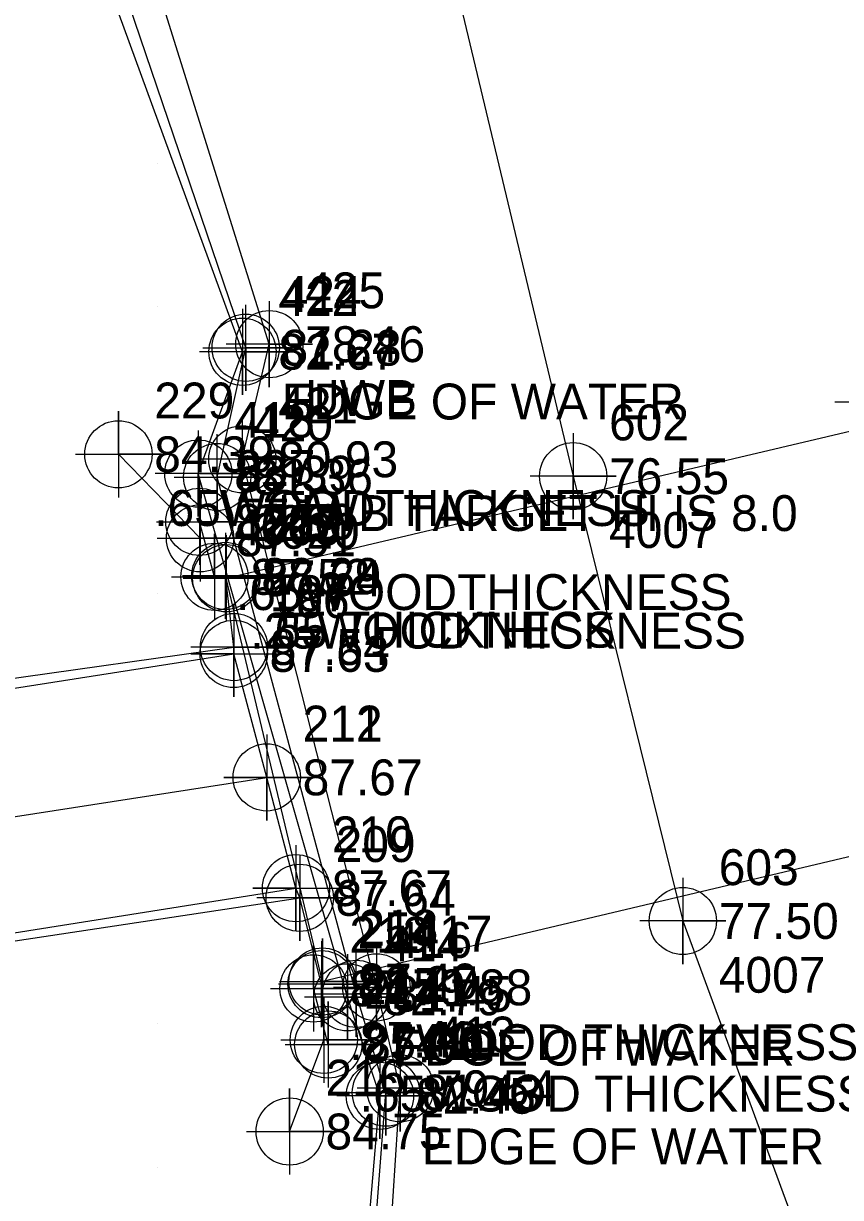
# Model space of a CAD drawing. Extents: x 1988140 to 1988766, y 249950 to 250250.
# Drawn here: x 1988400.7 to 1988457.6, y 250027.9 to 250109.7 of the extents above; entities that cross this region are included whole.
import ezdxf

# ---------------------------------------------------------------- set-up
doc = ezdxf.new("R2010")
doc.units = 0
for name, color, linetype in [('Exist DTM Breakline', 7, 'Continuous'), ('Exist DTM Breakline Cogo Comment', 7, 'Continuous'), ('Exist DTM Breakline Cogo Elevation', 7, 'Continuous'), ('Exist DTM Breakline Cogo Number', 7, 'Continuous'), ('Exist DTM Breakline Cogo Point CELL', 7, 'Continuous'), ('Exist DTM Breakline Underwater', 7, 'Continuous'), ('Exist DTM Breakline Underwater Cogo Comment', 7, 'Continuous'), ('Exist DTM Breakline Underwater Cogo Elevation', 7, 'Continuous'), ('Exist DTM Breakline Underwater Cogo Number', 7, 'Continuous'), ('Exist DTM Breakline Underwater Cogo Point CELL', 7, 'Continuous'), ('Exist DTM Crownline', 7, 'Continuous'), ('Exist DTM Crownline Cogo Elevation', 7, 'Continuous'), ('Exist DTM Crownline Cogo Number', 7, 'Continuous'), ('Exist DTM Crownline Cogo Point CELL', 7, 'Continuous'), ('Exist DTM QL2 LIDAR Elevation Point', 7, 'Continuous'), ('Exist Hydro Stream or Body of Water', 7, 'Continuous'), ('Exist Hydro Stream or Body of Water Cogo Comment', 7, 'Continuous'), ('Exist Hydro Stream or Body of Water Cogo Elevation', 7, 'Continuous'), ('Exist Hydro Stream or Body of Water Cogo Number', 7, 'Continuous'), ('Exist Hydro Stream or Body of Water Cogo Point CELL', 7, 'Continuous'), ('Exist Roads Change in Surface', 7, 'Continuous'), ('Exist Roads EOP', 7, 'Continuous'), ('Exist Roads EOP Cogo Comment', 7, 'Continuous'), ('Exist Roads EOP Cogo Elevation', 7, 'Continuous'), ('Exist Roads EOP Cogo Number', 7, 'Continuous'), ('Exist Roads EOP Cogo Point CELL', 7, 'Continuous'), ('Exist Roads EOT', 7, 'Continuous'), ('Exist Roads EOT Cogo Elevation', 7, 'Continuous'), ('Exist Roads EOT Cogo Number', 7, 'Continuous'), ('Exist Roads EOT Cogo Point CELL', 7, 'Continuous'), ('Exist Structure Major Bridge WW', 7, 'Continuous'), ('Exist Structure Major Deck Tunnel Box Culvert', 7, 'Continuous'), ('Exist Structure Major Deck Tunnel Box Culvert Cogo Elevation', 7, 'Continuous'), ('Exist Structure Major Deck Tunnel Box Culvert Cogo Number', 7, 'Continuous'), ('Exist Structure Major Deck Tunnel Box Culvert Cogo Point CELL', 7, 'Continuous'), ('Exist Structure Minor Head and End Wall Cogo Comment', 7, 'Continuous'), ('Exist Structure Minor Head and End Wall Cogo Elevation', 7, 'Continuous'), ('Exist Structure Minor Head and End Wall Cogo Number', 7, 'Continuous'), ('Exist Structure Minor Head and End Wall Cogo Point CELL', 7, 'Continuous')]:
    doc.layers.add(name, color=color, linetype=linetype)

msp = doc.modelspace()

# ---------------------------------------------------------------- linework, layer by layer
at = {"layer": 'Exist DTM Breakline'}
for points in [[(1988412.8446, 250078.35), (1988415.9225, 250086.8449), (1988404.9645, 250116.8632), (1988400.2626, 250127.7783), (1988397.8753, 250146.5011), (1988407.465, 250191.587)], [(1988432.5356, 249952.6918), (1988424.6294, 249989.0571), (1988424.2247, 250020.0082), (1988425.5053, 250034.9767), (1988423.2372, 250041.8418), (1988412.8446, 250078.35)]]:
    msp.add_lwpolyline(points, dxfattribs=at)
at = {"layer": 'Exist DTM Breakline Cogo Point CELL'}
for points in [[(1988417.7936, 250090.3716), (1988417.7936, 250084.3716), (1988417.7936, 250087.3716), (1988420.7936, 250087.3716), (1988414.7936, 250087.3716)], [(1988415.9225, 250089.8449), (1988415.9225, 250083.8449), (1988415.9225, 250086.8449), (1988418.9225, 250086.8449), (1988412.9225, 250086.8449)], [(1988460.2177, 250086.319), (1988460.2177, 250080.319), (1988460.2177, 250083.319), (1988463.2177, 250083.319), (1988457.2177, 250083.319)], [(1988415.9105, 250082.3465), (1988415.9105, 250076.3465), (1988415.9105, 250079.3465), (1988418.9105, 250079.3465), (1988412.9105, 250079.3465)], [(1988412.8446, 250081.35), (1988412.8446, 250075.35), (1988412.8446, 250078.35), (1988415.8446, 250078.35), (1988409.8446, 250078.35)], [(1988425.2614, 250045.5346), (1988425.2614, 250039.5346), (1988425.2614, 250042.5346), (1988428.2614, 250042.5346), (1988422.2614, 250042.5346)], [(1988423.2372, 250044.8418), (1988423.2372, 250038.8418), (1988423.2372, 250041.8418), (1988426.2372, 250041.8418), (1988420.2372, 250041.8418)], [(1988426.9175, 250038.4976), (1988426.9175, 250032.4976), (1988426.9175, 250035.4976), (1988429.9175, 250035.4976), (1988423.9175, 250035.4976)], [(1988425.5053, 250037.9767), (1988425.5053, 250031.9767), (1988425.5053, 250034.9767), (1988428.5053, 250034.9767), (1988422.5053, 250034.9767)]]:
    msp.add_lwpolyline(points, dxfattribs=at)
for centre in [(1988415.9225, 250086.8449), (1988417.7936, 250087.3716), (1988415.9105, 250079.3465), (1988412.8446, 250078.35), (1988423.2372, 250041.8418), (1988425.2614, 250042.5346), (1988426.9175, 250035.4976), (1988425.5053, 250034.9767)]:
    msp.add_circle(centre, 2.344, dxfattribs=at)
at = {"layer": 'Exist DTM Breakline Underwater'}
for points in [[(1988432.5434, 250186.7094), (1988425.7037, 250133.7144), (1988438.98, 250078.1677), (1988446.627, 250047.162), (1988463.2661, 250001.9742), (1988462.1612, 249955.3502)], [(1988417.7936, 250087.3716), (1988408.4707, 250117.1773), (1988402.0332, 250128.5975)], [(1988436.1327, 249955.9094), (1988427.138, 249990.9941), (1988425.95, 250020.4466), (1988426.9175, 250035.4976), (1988425.2614, 250042.5346), (1988415.9105, 250079.3465), (1988417.7936, 250087.3716)]]:
    msp.add_lwpolyline(points, dxfattribs=at)
at = {"layer": 'Exist DTM Breakline Underwater Cogo Point CELL'}
for points in [[(1988438.98, 250081.1677), (1988438.98, 250075.1677), (1988438.98, 250078.1677), (1988441.98, 250078.1677), (1988435.98, 250078.1677)], [(1988446.627, 250050.162), (1988446.627, 250044.162), (1988446.627, 250047.162), (1988449.627, 250047.162), (1988443.627, 250047.162)]]:
    msp.add_lwpolyline(points, dxfattribs=at)
for centre in [(1988438.98, 250078.1677), (1988446.627, 250047.162)]:
    msp.add_circle(centre, 2.344, dxfattribs=at)
at = {"layer": 'Exist DTM Crownline'}
msp.add_lwpolyline([(1988342.6848, 250048.4444), (1988378.1968, 250051.0543), (1988417.6158, 250057.1729)], dxfattribs=at)
at = {"layer": 'Exist DTM Crownline Cogo Point CELL'}
msp.add_lwpolyline([(1988417.6158, 250060.1729), (1988417.6158, 250054.1729), (1988417.6158, 250057.1729), (1988420.6158, 250057.1729), (1988414.6158, 250057.1729)], dxfattribs=at)
msp.add_circle((1988417.6158, 250057.1729), 2.344, dxfattribs=at)
at = {"layer": 'Exist DTM QL2 LIDAR Elevation Point'}
for p, q in [((1988410, 250100), (1988410, 250100)), ((1988410, 250090), (1988410, 250090)), ((1988410, 250070), (1988410, 250070)), ((1988410, 250040), (1988410, 250040)), ((1988410, 250030), (1988410, 250030)), ((1988420, 250030), (1988420, 250030))]:
    msp.add_line(p, q, dxfattribs=at)
at = {"layer": 'Exist Hydro Stream or Body of Water'}
msp.add_lwpolyline([(1988426.3876, 249990.4525), (1988424.7619, 250020.0506), (1988425.9258, 250035.2006), (1988423.8559, 250042.0862), (1988414.1552, 250078.1093), (1988416.1489, 250087.1232), (1988406.0862, 250116.7149), (1988400.9098, 250127.7446), (1988403.8774, 250149.9815), (1988410.3915, 250190.2759)], dxfattribs=at)
at = {"layer": 'Exist Hydro Stream or Body of Water Cogo Point CELL'}
for points in [[(1988413.1489, 250087.1232), (1988419.1489, 250087.1232), (1988416.1489, 250087.1232), (1988416.1489, 250084.1232), (1988416.1489, 250090.1232)], [(1988411.1552, 250078.1093), (1988417.1552, 250078.1093), (1988414.1552, 250078.1093), (1988414.1552, 250075.1093), (1988414.1552, 250081.1093)], [(1988420.8559, 250042.0862), (1988426.8559, 250042.0862), (1988423.8559, 250042.0862), (1988423.8559, 250039.0862), (1988423.8559, 250045.0862)], [(1988422.9258, 250035.2006), (1988428.9258, 250035.2006), (1988425.9258, 250035.2006), (1988425.9258, 250032.2006), (1988425.9258, 250038.2006)]]:
    msp.add_lwpolyline(points, dxfattribs=at)
for centre in [(1988416.1489, 250087.1232), (1988414.1552, 250078.1093), (1988423.8559, 250042.0862), (1988425.9258, 250035.2006)]:
    msp.add_circle(centre, 2.344, dxfattribs=at)
at = {"layer": 'Exist Roads Change in Surface'}
msp.add_lwpolyline([(1988421.4394, 250042.7581), (1988419.9154, 250048.7733), (1988419.6541, 250049.4523), (1988417.6158, 250057.1729), (1988415.3125, 250065.7797), (1988415.3306, 250066.2585), (1988414.7331, 250071.2154)], dxfattribs=at)
at = {"layer": 'Exist Roads EOP'}
for p, q in [((1988376.5794, 250060.7743), (1988415.3306, 250066.2585)), ((1988378.4174, 250042.5183), (1988419.9154, 250048.7733))]:
    msp.add_line(p, q, dxfattribs=at)
at = {"layer": 'Exist Roads EOP Cogo Point CELL'}
for points in [[(1988414.7331, 250074.2154), (1988414.7331, 250068.2154), (1988414.7331, 250071.2154), (1988417.7331, 250071.2154), (1988411.7331, 250071.2154)], [(1988415.3306, 250069.2585), (1988415.3306, 250063.2585), (1988415.3306, 250066.2585), (1988418.3306, 250066.2585), (1988412.3306, 250066.2585)], [(1988419.9154, 250051.7733), (1988419.9154, 250045.7733), (1988419.9154, 250048.7733), (1988422.9154, 250048.7733), (1988416.9154, 250048.7733)], [(1988421.4394, 250045.7581), (1988421.4394, 250039.7581), (1988421.4394, 250042.7581), (1988424.4394, 250042.7581), (1988418.4394, 250042.7581)]]:
    msp.add_lwpolyline(points, dxfattribs=at)
for centre in [(1988414.7331, 250071.2154), (1988415.3306, 250066.2585), (1988419.9154, 250048.7733), (1988421.4394, 250042.7581)]:
    msp.add_circle(centre, 2.344, dxfattribs=at)
at = {"layer": 'Exist Roads EOT'}
msp.add_line((1988376.6581, 250059.7647), (1988415.3125, 250065.7797), dxfattribs=at)
msp.add_lwpolyline([(1988378.4449, 250042.9134), (1988419.6541, 250049.4523)], dxfattribs=at)
at = {"layer": 'Exist Roads EOT Cogo Point CELL'}
for points in [[(1988415.3125, 250068.7797), (1988415.3125, 250062.7797), (1988415.3125, 250065.7797), (1988412.3125, 250065.7797), (1988418.3125, 250065.7797)], [(1988417.6158, 250060.1729), (1988417.6158, 250054.1729), (1988417.6158, 250057.1729), (1988414.6158, 250057.1729), (1988420.6158, 250057.1729)], [(1988419.6541, 250052.4523), (1988419.6541, 250046.4523), (1988419.6541, 250049.4523), (1988416.6541, 250049.4523), (1988422.6541, 250049.4523)]]:
    msp.add_lwpolyline(points, dxfattribs=at)
for centre in [(1988415.3125, 250065.7797), (1988417.6158, 250057.1729), (1988419.6541, 250049.4523)]:
    msp.add_circle(centre, 2.344, dxfattribs=at)
at = {"layer": 'Exist Structure Major Bridge WW'}
for p, q in [((1988412.9686, 250073.8373), (1988407.2724, 250079.6949)), ((1988413.9758, 250071.1517), (1988412.9223, 250074.9902)), ((1988421.9052, 250038.5551), (1988420.8774, 250042.463)), ((1988419.2102, 250032.486), (1988421.5974, 250038.8772))]:
    msp.add_line(p, q, dxfattribs=at)
at = {"layer": 'Exist Structure Major Deck Tunnel Box Culvert'}
msp.add_lwpolyline([(1988414.7923, 250071.0539), (1988472.9466, 250084.7703), (1988479.6979, 250056.7161), (1988421.5011, 250042.945)], close=True, dxfattribs=at)
at = {"layer": 'Exist Structure Major Deck Tunnel Box Culvert Cogo Point CELL'}
for points in [[(1988411.7923, 250071.0539), (1988417.7923, 250071.0539), (1988414.7923, 250071.0539), (1988414.7923, 250074.0539), (1988414.7923, 250068.0539)], [(1988418.5011, 250042.945), (1988424.5011, 250042.945), (1988421.5011, 250042.945), (1988421.5011, 250045.945), (1988421.5011, 250039.945)]]:
    msp.add_lwpolyline(points, dxfattribs=at)
for centre in [(1988414.7923, 250071.0539), (1988421.5011, 250042.945)]:
    msp.add_circle(centre, 2.344, dxfattribs=at)
at = {"layer": 'Exist Structure Minor Head and End Wall Cogo Point CELL'}
for points in [[(1988404.2724, 250079.6949), (1988410.2724, 250079.6949), (1988407.2724, 250079.6949), (1988407.2724, 250082.6949), (1988407.2724, 250076.6949)], [(1988409.9223, 250074.9902), (1988415.9223, 250074.9902), (1988412.9223, 250074.9902), (1988412.9223, 250077.9902), (1988412.9223, 250071.9902)], [(1988409.9686, 250073.8373), (1988415.9686, 250073.8373), (1988412.9686, 250073.8373), (1988412.9686, 250076.8373), (1988412.9686, 250070.8373)], [(1988410.9758, 250071.1517), (1988416.9758, 250071.1517), (1988413.9758, 250071.1517), (1988413.9758, 250074.1517), (1988413.9758, 250068.1517)], [(1988417.8774, 250042.463), (1988423.8774, 250042.463), (1988420.8774, 250042.463), (1988420.8774, 250045.463), (1988420.8774, 250039.463)], [(1988418.5974, 250038.8772), (1988424.5974, 250038.8772), (1988421.5974, 250038.8772), (1988421.5974, 250041.8772), (1988421.5974, 250035.8772)], [(1988418.9052, 250038.5551), (1988424.9052, 250038.5551), (1988421.9052, 250038.5551), (1988421.9052, 250041.5551), (1988421.9052, 250035.5551)], [(1988416.2102, 250032.486), (1988422.2102, 250032.486), (1988419.2102, 250032.486), (1988419.2102, 250035.486), (1988419.2102, 250029.486)]]:
    msp.add_lwpolyline(points, dxfattribs=at)
for centre in [(1988407.2724, 250079.6949), (1988412.9223, 250074.9902), (1988412.9686, 250073.8373), (1988413.9758, 250071.1517), (1988420.8774, 250042.463), (1988421.5974, 250038.8772), (1988421.9052, 250038.5551), (1988419.2102, 250032.486)]:
    msp.add_circle(centre, 2.344, dxfattribs=at)

# ---------------------------------------------------------------- texts
at = {"layer": 'Exist DTM Breakline Cogo Comment'}
for s, p in [('UWB', (1988420.2936, 250082.3716)), ('UWB TARGET HI IS 8.0', (1988418.4105, 250074.3465)), ('4005', (1988415.3446, 250073.35))]:
    msp.add_text(s, height=2.5, dxfattribs=at).set_placement(p)
at = {"layer": 'Exist DTM Breakline Cogo Elevation'}
for s, p in [('78.46', (1988420.2936, 250086.1216)), ('82.67', (1988418.4225, 250085.5949)), ('80.93', (1988418.4105, 250078.0965)), ('83.39', (1988415.3446, 250077.1)), ('79.88', (1988427.7614, 250041.2846)), ('82.79', (1988425.7372, 250040.5918)), ('79.54', (1988429.4175, 250034.2476)), ('82.45', (1988428.0053, 250033.7267))]:
    msp.add_text(s, height=2.5, dxfattribs=at).set_placement(p)
at = {"layer": 'Exist DTM Breakline Cogo Number'}
for s, p in [('425', (1988420.2936, 250089.8716)), ('422', (1988418.4225, 250089.3449)), ('421', (1988418.4105, 250081.8465)), ('418', (1988415.3446, 250080.85)), ('417', (1988427.7614, 250045.0346)), ('414', (1988425.7372, 250044.3418)), ('413', (1988429.4175, 250037.9976)), ('410', (1988428.0053, 250037.4767))]:
    msp.add_text(s, height=2.5, dxfattribs=at).set_placement(p)
at = {"layer": 'Exist DTM Breakline Underwater Cogo Comment'}
for p in [(1988441.48, 250073.1677), (1988449.127, 250042.162)]:
    msp.add_text('4007', height=2.5, dxfattribs=at).set_placement(p)
at = {"layer": 'Exist DTM Breakline Underwater Cogo Elevation'}
for s, p in [('76.55', (1988441.48, 250076.9177)), ('77.50', (1988449.127, 250045.912))]:
    msp.add_text(s, height=2.5, dxfattribs=at).set_placement(p)
at = {"layer": 'Exist DTM Breakline Underwater Cogo Number'}
for s, p in [('602', (1988441.48, 250080.6677)), ('603', (1988449.127, 250049.662))]:
    msp.add_text(s, height=2.5, dxfattribs=at).set_placement(p)
at = {"layer": 'Exist DTM Crownline Cogo Elevation'}
msp.add_text('87.67', height=2.5, dxfattribs=at).set_placement((1988420.1158, 250055.9229))
at = {"layer": 'Exist DTM Crownline Cogo Number'}
msp.add_text('211', height=2.5, dxfattribs=at).set_placement((1988420.1158, 250059.6729))
at = {"layer": 'Exist Hydro Stream or Body of Water Cogo Comment'}
for s, p in [('EDGE OF WATER', (1988418.6489, 250082.1232)), ('3620', (1988416.6552, 250073.1093)), ('EDGE OF WATER', (1988426.3559, 250037.0862)), ('EDGE OF WATER', (1988428.4258, 250030.2006))]:
    msp.add_text(s, height=2.5, dxfattribs=at).set_placement(p)
at = {"layer": 'Exist Hydro Stream or Body of Water Cogo Elevation'}
for s, p in [('81.28', (1988418.6489, 250085.8732)), ('81.36', (1988416.6552, 250076.8593)), ('81.45', (1988426.3559, 250040.8362)), ('81.43', (1988428.4258, 250033.9506))]:
    msp.add_text(s, height=2.5, dxfattribs=at).set_placement(p)
at = {"layer": 'Exist Hydro Stream or Body of Water Cogo Number'}
for s, p in [('424', (1988418.6489, 250089.6232)), ('420', (1988416.6552, 250080.6093)), ('416', (1988426.3559, 250044.5862)), ('411', (1988428.4258, 250037.7006))]:
    msp.add_text(s, height=2.5, dxfattribs=at).set_placement(p)
at = {"layer": 'Exist Roads EOP Cogo Comment'}
msp.add_text('.65 THICKNESS', height=2.5, dxfattribs=at).set_placement((1988417.2331, 250066.2154))
at = {"layer": 'Exist Roads EOP Cogo Elevation'}
for s, p in [('88.29', (1988417.2331, 250069.9654)), ('87.54', (1988417.8306, 250065.0085)), ('87.64', (1988422.4154, 250047.5233)), ('88.27', (1988423.9394, 250041.5081))]:
    msp.add_text(s, height=2.5, dxfattribs=at).set_placement(p)
at = {"layer": 'Exist Roads EOP Cogo Number'}
for s, p in [('220', (1988417.2331, 250073.7154)), ('187', (1988417.8306, 250068.7585)), ('209', (1988422.4154, 250051.2733)), ('254', (1988423.9394, 250045.2581))]:
    msp.add_text(s, height=2.5, dxfattribs=at).set_placement(p)
at = {"layer": 'Exist Roads EOT Cogo Elevation'}
for s, p in [('87.63', (1988417.8125, 250064.5297)), ('87.67', (1988420.1158, 250055.9229)), ('87.67', (1988422.1541, 250048.2023))]:
    msp.add_text(s, height=2.5, dxfattribs=at).set_placement(p)
at = {"layer": 'Exist Roads EOT Cogo Number'}
for s, p in [('186', (1988417.8125, 250068.2797)), ('212', (1988420.1158, 250059.6729)), ('210', (1988422.1541, 250051.9523))]:
    msp.add_text(s, height=2.5, dxfattribs=at).set_placement(p)
at = {"layer": 'Exist Structure Major Deck Tunnel Box Culvert Cogo Elevation'}
for s, p in [('87.64', (1988417.2923, 250069.8039)), ('87.40', (1988424.0011, 250041.695))]:
    msp.add_text(s, height=2.5, dxfattribs=at).set_placement(p)
at = {"layer": 'Exist Structure Major Deck Tunnel Box Culvert Cogo Number'}
for s, p in [('219', (1988417.2923, 250073.5539)), ('218', (1988424.0011, 250045.445))]:
    msp.add_text(s, height=2.5, dxfattribs=at).set_placement(p)
at = {"layer": 'Exist Structure Minor Head and End Wall Cogo Comment'}
for s, p in [('.65WOODTHICKNESS', (1988409.7724, 250074.6949)), ('.65WOODTHICKNESS', (1988415.4686, 250068.8373)), ('.25WOODTHICKNESS', (1988416.4758, 250066.1517)), ('.25WOOD THICKNESS', (1988423.3774, 250037.463)), ('.65WOOD THICKNESS', (1988424.0974, 250033.8772))]:
    msp.add_text(s, height=2.5, dxfattribs=at).set_placement(p)
at = {"layer": 'Exist Structure Minor Head and End Wall Cogo Elevation'}
for s, p in [('84.39', (1988409.7724, 250078.4449)), ('87.50', (1988415.4223, 250073.7402)), ('87.51', (1988415.4686, 250072.5873)), ('87.52', (1988416.4758, 250069.9017)), ('87.41', (1988423.3774, 250041.213)), ('87.43', (1988424.0974, 250037.6272)), ('87.30', (1988424.4052, 250037.3051)), ('84.75', (1988421.7102, 250031.236))]:
    msp.add_text(s, height=2.5, dxfattribs=at).set_placement(p)
at = {"layer": 'Exist Structure Minor Head and End Wall Cogo Number'}
for s, p in [('229', (1988409.7724, 250082.1949)), ('227', (1988415.4223, 250077.4902)), ('228', (1988415.4686, 250076.3373)), ('226', (1988416.4758, 250073.6517)), ('213', (1988423.3774, 250044.963)), ('215', (1988424.0974, 250041.3772)), ('214', (1988424.4052, 250041.0551)), ('216', (1988421.7102, 250034.986))]:
    msp.add_text(s, height=2.5, dxfattribs=at).set_placement(p)

doc.saveas('drawing.dxf')
